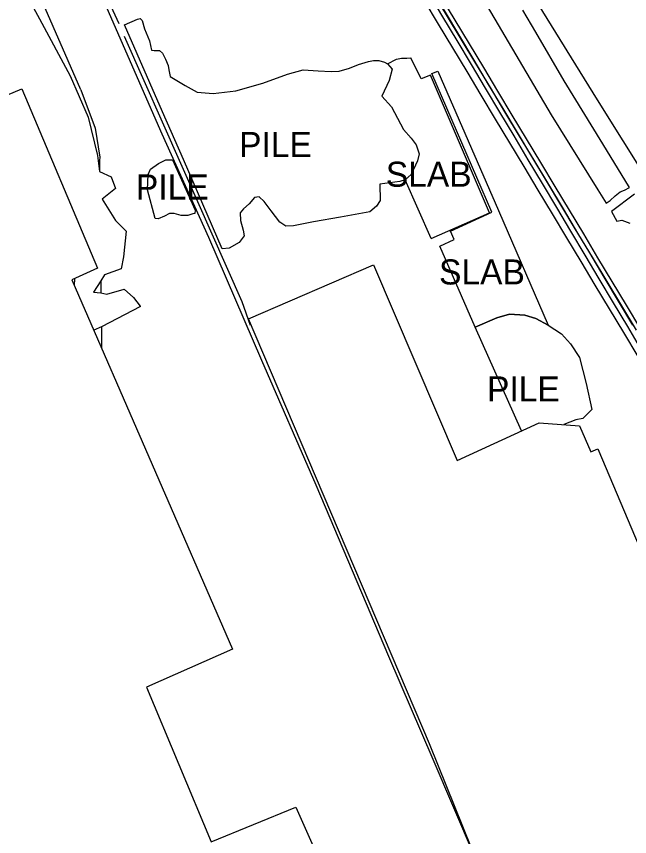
# Model space of a CAD drawing. Extents: x 368532 to 392481, y 10654822 to 10676899.
# Drawn here: x 378537.6 to 378659.8, y 10661264.3 to 10661427.9 of the extents above; entities that cross this region are included whole.
import ezdxf

# ---------------------------------------------------------------- set-up
doc = ezdxf.new("R2010")
doc.units = 0
for name, color, linetype in [('p_Catenary', 7, 'Continuous'), ('p_dtm retaining wall', 7, 'Continuous'), ('p_dtm sidewalk', 7, 'Continuous'), ('p_dtm slab', 7, 'Continuous'), ('p_dtm stock pile', 7, 'Continuous'), ('p_road - paved curb', 7, 'Continuous'), ('p_road general road feature', 7, 'Continuous'), ('p_structure building', 7, 'Continuous')]:
    doc.layers.add(name, color=color, linetype=linetype)

msp = doc.modelspace()

# ---------------------------------------------------------------- linework, layer by layer
at = {"layer": 'p_Catenary'}
for points in [[(378611.47, 10661447.94), (378614.35, 10661443.13), (378617.23, 10661438.33), (378620.1, 10661433.53), (378622.98, 10661428.73), (378625.86, 10661423.93), (378628.74, 10661419.12), (378631.61, 10661414.32), (378634.49, 10661409.52), (378637.37, 10661404.72), (378640.24, 10661399.92), (378643.12, 10661395.11), (378646, 10661390.31), (378648.88, 10661385.51), (378651.75, 10661380.71), (378654.63, 10661375.91), (378657.51, 10661371.11), (378660.38, 10661366.3)], [(378611.59, 10661447.53), (378614.5, 10661442.7), (378617.41, 10661437.86), (378620.32, 10661433.03), (378623.23, 10661428.19), (378626.13, 10661423.36), (378629.04, 10661418.52), (378631.95, 10661413.69), (378634.86, 10661408.85), (378637.77, 10661404.02), (378640.68, 10661399.18), (378643.59, 10661394.35), (378646.5, 10661389.51), (378649.41, 10661384.68), (378652.32, 10661379.84), (378655.23, 10661375.01), (378658.14, 10661370.17), (378661.05, 10661365.34)], [(378611.17, 10661446.81), (378614.01, 10661442.06), (378616.84, 10661437.31), (378619.67, 10661432.56), (378622.51, 10661427.81), (378625.34, 10661423.06), (378628.17, 10661418.31), (378631.01, 10661413.55), (378633.84, 10661408.8), (378636.67, 10661404.05), (378639.51, 10661399.3), (378642.34, 10661394.55), (378645.17, 10661389.8), (378648.01, 10661385.05), (378650.84, 10661380.29), (378653.67, 10661375.54), (378656.51, 10661370.79), (378659.34, 10661366.04), (378662.17, 10661361.29)], [(378613.55, 10661446.12), (378616.39, 10661441.38), (378619.24, 10661436.64), (378622.09, 10661431.9), (378624.93, 10661427.16), (378627.78, 10661422.42), (378630.63, 10661417.68), (378633.47, 10661412.94), (378636.32, 10661408.2), (378639.16, 10661403.46), (378642.01, 10661398.72), (378644.86, 10661393.98), (378647.7, 10661389.24), (378650.55, 10661384.5), (378653.4, 10661379.76), (378656.24, 10661375.02), (378659.09, 10661370.28), (378661.94, 10661365.54)], [(378610.27, 10661445.29), (378613.11, 10661440.56), (378615.95, 10661435.83), (378618.79, 10661431.09), (378621.63, 10661426.36), (378624.47, 10661421.62), (378627.31, 10661416.89), (378630.15, 10661412.16), (378632.99, 10661407.42), (378635.83, 10661402.69), (378638.67, 10661397.95), (378641.51, 10661393.22), (378644.35, 10661388.49), (378647.19, 10661383.75), (378650.03, 10661379.02), (378652.87, 10661374.28), (378655.71, 10661369.55), (378658.55, 10661364.82), (378661.39, 10661360.08)]]:
    msp.add_lwpolyline(points, dxfattribs=at)
at = {"layer": 'p_dtm retaining wall'}
for p, q in [((378540.16, 10661466.05), (378557.94, 10661426.45)), ((378559.05, 10661423.95), (378570.53, 10661398.01)), ((378570.53, 10661398.01), (378582.46, 10661371.06)), ((378582.46, 10661371.06), (378584.15, 10661366.3))]:
    msp.add_line(p, q, dxfattribs=at)
at = {"layer": 'p_dtm sidewalk'}
for p, q in [((378631.35, 10661429.9), (378644.17, 10661408.24)), ((378641.06, 10661424.73), (378638.51, 10661429.1)), ((378646.75, 10661415.06), (378641.06, 10661424.73)), ((378654.46, 10661402.48), (378646.75, 10661415.06)), ((378644.17, 10661408.24), (378653.41, 10661393.29)), ((378659.73, 10661393.79), (378654.46, 10661402.48)), ((378653.41, 10661393.29), (378655.07, 10661390.65)), ((378657.91, 10661392.87), (378658.77, 10661393.25)), ((378658.77, 10661393.25), (378659.73, 10661393.79)), ((378655.88, 10661391.19), (378656.88, 10661392.1)), ((378660.73, 10661392.41), (378656.17, 10661388.96)), ((378656.88, 10661392.1), (378657.91, 10661392.87)), ((378655.07, 10661390.65), (378655.88, 10661391.19)), ((378656.17, 10661388.96), (378657.2, 10661387.07)), ((378657.2, 10661387.07), (378658.25, 10661387.28)), ((378658.25, 10661387.28), (378659.81, 10661386.62))]:
    msp.add_line(p, q, dxfattribs=at)
at = {"layer": 'p_dtm slab'}
for p, q in [((378611.5, 10661418.45), (378613.29, 10661419.37)), ((378613.29, 10661419.37), (378614.33, 10661419.54)), ((378614.33, 10661419.54), (378615.4, 10661419.56)), ((378615.4, 10661419.56), (378616.2, 10661419.65)), ((378618.22, 10661415.4), (378616.2, 10661419.65)), ((378620.11, 10661416.15), (378618.22, 10661415.4)), ((378631.88, 10661388.69), (378620.11, 10661416.15)), ((378620.33, 10661416.47), (378621.52, 10661416.99)), ((378632.28, 10661388.82), (378620.33, 10661416.47)), ((378621.52, 10661416.99), (378633.62, 10661389.18)), ((378620.23, 10661383.6), (378615.04, 10661395.29)), ((378620.23, 10661383.6), (378631.88, 10661388.69)), ((378624.06, 10661385.05), (378632.28, 10661388.82)), ((378633.62, 10661389.18), (378643.52, 10661366.34)), ((378624.82, 10661383.42), (378624.06, 10661385.05)), ((378621.98, 10661382.03), (378624.82, 10661383.42)), ((378629.02, 10661365.93), (378621.98, 10661382.03)), ((378635.84, 10661368.5), (378633.3, 10661367.74)), ((378638.89, 10661368.31), (378635.84, 10661368.5)), ((378633.3, 10661367.74), (378629.02, 10661365.93)), ((378641.08, 10661367.67), (378638.89, 10661368.31)), ((378643.52, 10661366.34), (378641.08, 10661367.67))]:
    msp.add_line(p, q, dxfattribs=at)
at = {"layer": 'p_dtm stock pile'}
for p, q in [((378537.92, 10661435.15), (378542.16, 10661427.37)), ((378542.16, 10661427.37), (378548.27, 10661416.05)), ((378561.68, 10661427.34), (378562.25, 10661427.46)), ((378562.25, 10661427.46), (378562.61, 10661427.04)), ((378559.12, 10661426.23), (378561.68, 10661427.34)), ((378566.68, 10661408.82), (378559.12, 10661426.23)), ((378562.61, 10661427.04), (378563.07, 10661425.39)), ((378563.07, 10661425.39), (378564.06, 10661423.04)), ((378564.06, 10661423.04), (378564.5, 10661421.12)), ((378564.5, 10661421.12), (378564.98, 10661421.07)), ((378564.98, 10661421.07), (378566.09, 10661421.11)), ((378566.09, 10661421.11), (378566.68, 10661420.55)), ((378566.68, 10661420.55), (378567.3, 10661419.35)), ((378567.3, 10661419.35), (378567.77, 10661418.09)), ((378567.77, 10661418.09), (378567.95, 10661417.25)), ((378603.96, 10661417.54), (378605.76, 10661418.26)), ((378605.76, 10661418.26), (378607.73, 10661418.92)), ((378607.73, 10661418.92), (378608.72, 10661419.1)), ((378608.72, 10661419.1), (378609.8, 10661419.09)), ((378609.8, 10661419.09), (378610.93, 10661418.76)), ((378610.93, 10661418.76), (378611.5, 10661418.45)), ((378611.5, 10661418.45), (378612.48, 10661417.39)), ((378548.27, 10661416.05), (378551.88, 10661407.78)), ((378567.95, 10661417.25), (378568.22, 10661415.9)), ((378586.67, 10661414.58), (378591.57, 10661416.35)), ((378591.57, 10661416.35), (378594.72, 10661417.22)), ((378594.72, 10661417.22), (378597.67, 10661417)), ((378597.67, 10661417), (378600.28, 10661416.87)), ((378600.28, 10661416.87), (378601.87, 10661416.94)), ((378601.87, 10661416.94), (378603.96, 10661417.54)), ((378612.48, 10661417.39), (378611.86, 10661415.09)), ((378568.22, 10661415.9), (378571.2, 10661414.1)), ((378581.27, 10661413.02), (378586.67, 10661414.58)), ((378611.86, 10661415.09), (378610.38, 10661411.97)), ((378571.2, 10661414.1), (378573.57, 10661412.8)), ((378573.57, 10661412.8), (378576.74, 10661412.53)), ((378576.74, 10661412.53), (378581.27, 10661413.02)), ((378610.38, 10661411.97), (378612.3, 10661409.85)), ((378612.3, 10661409.85), (378614.7, 10661405.3)), ((378551.88, 10661407.78), (378553.69, 10661400.11)), ((378570.84, 10661399.37), (378566.68, 10661408.82)), ((378614.7, 10661405.3), (378616.25, 10661403.57)), ((378616.25, 10661403.57), (378617.24, 10661402.27)), ((378617.24, 10661402.27), (378617.8, 10661400.5)), ((378553.69, 10661400.11), (378554.11, 10661396.98)), ((378617.8, 10661400.5), (378617.52, 10661399.1)), ((378564.28, 10661397.45), (378565.85, 10661398.57)), ((378565.85, 10661398.57), (378567.34, 10661399.26)), ((378567.34, 10661399.26), (378568.66, 10661399.3)), ((378568.66, 10661399.3), (378573.17, 10661389.21)), ((378578.54, 10661381.51), (378570.84, 10661399.37)), ((378617.52, 10661399.1), (378616.24, 10661396.35)), ((378554.11, 10661396.98), (378556.43, 10661395.88)), ((378563.68, 10661393.3), (378563.79, 10661396.33)), ((378563.79, 10661396.33), (378564.28, 10661397.45)), ((378616.24, 10661396.35), (378615.04, 10661395.29)), ((378556.43, 10661395.88), (378557.32, 10661393.55)), ((378614, 10661394.99), (378609.97, 10661394.44)), ((378615.04, 10661395.29), (378614, 10661394.99)), ((378557.32, 10661393.55), (378554.63, 10661391.43)), ((378565.18, 10661387.6), (378563.68, 10661393.3)), ((378609.97, 10661394.44), (378610.05, 10661391.2)), ((378554.63, 10661391.43), (378557.33, 10661387.21)), ((378585.01, 10661391.75), (378583.94, 10661390.53)), ((378585.93, 10661391.88), (378585.01, 10661391.75)), ((378586.91, 10661390.98), (378585.93, 10661391.88)), ((378583.94, 10661390.53), (378582.84, 10661389.51)), ((378588.32, 10661389.12), (378586.91, 10661390.98)), ((378609.32, 10661390.06), (378608.01, 10661388.92)), ((378610.05, 10661391.2), (378609.32, 10661390.06)), ((378568.04, 10661388.59), (378567.09, 10661388.07)), ((378569.03, 10661388.56), (378568.04, 10661388.59)), ((378570.4, 10661388.16), (378569.03, 10661388.56)), ((378571.71, 10661388.19), (378570.4, 10661388.16)), ((378572.75, 10661388.48), (378571.71, 10661388.19)), ((378573.1, 10661388.59), (378572.75, 10661388.48)), ((378573.17, 10661389.21), (378573.1, 10661388.59)), ((378582.84, 10661389.51), (378582.14, 10661388.71)), ((378582.14, 10661388.71), (378582.24, 10661387.19)), ((378590.07, 10661386.86), (378588.32, 10661389.12)), ((378608.01, 10661388.92), (378602.18, 10661387.84)), ((378557.33, 10661387.21), (378559.44, 10661385.07)), ((378565.79, 10661387.53), (378565.18, 10661387.6)), ((378567.09, 10661388.07), (378565.79, 10661387.53)), ((378582.24, 10661387.19), (378582.74, 10661385.25)), ((378591.24, 10661386.04), (378590.07, 10661386.86)), ((378596.8, 10661386.94), (378592.81, 10661386.13)), ((378602.18, 10661387.84), (378596.8, 10661386.94)), ((378559.44, 10661385.07), (378558.89, 10661379.91)), ((378582.74, 10661385.25), (378582.96, 10661384.09)), ((378592.81, 10661386.13), (378591.24, 10661386.04)), ((378582.96, 10661384.09), (378581.95, 10661382.77)), ((378579.93, 10661381.68), (378578.54, 10661381.51)), ((378581.95, 10661382.77), (378579.93, 10661381.68)), ((378558.89, 10661379.91), (378558.43, 10661377.53)), ((378558.43, 10661377.53), (378555.12, 10661376.37)), ((378549.13, 10661374.18), (378549.2, 10661375.62)), ((378554.38, 10661375.16), (378552.89, 10661372.91)), ((378555.12, 10661376.37), (378554.38, 10661375.16)), ((378555.61, 10661372.52), (378559.02, 10661373.49)), ((378559.02, 10661373.49), (378560.86, 10661371.85)), ((378552.89, 10661372.91), (378554.4, 10661372.78)), ((378554.4, 10661372.78), (378555.61, 10661372.52)), ((378560.86, 10661371.85), (378562.25, 10661370.1)), ((378562.28, 10661370.02), (378554.49, 10661365.97)), ((378562.25, 10661370.1), (378562.28, 10661370.02)), ((378633.3, 10661367.74), (378635.84, 10661368.5)), ((378635.84, 10661368.5), (378638.89, 10661368.31)), ((378629.02, 10661365.93), (378633.3, 10661367.74)), ((378638.89, 10661368.31), (378641.08, 10661367.67)), ((378641.08, 10661367.67), (378643.52, 10661366.34)), ((378554.49, 10661365.97), (378552.97, 10661365.34)), ((378638.22, 10661345.24), (378629.02, 10661365.93)), ((378643.52, 10661366.34), (378646.23, 10661364.61)), ((378646.23, 10661364.61), (378648, 10661362.6)), ((378648, 10661362.6), (378649.77, 10661359.86)), ((378649.77, 10661359.86), (378651.14, 10661354.69)), ((378651.14, 10661354.69), (378652.22, 10661349.48)), ((378652.22, 10661349.48), (378650.44, 10661347.73)), ((378649.05, 10661347.43), (378646.63, 10661346.47)), ((378650.44, 10661347.73), (378649.05, 10661347.43))]:
    msp.add_line(p, q, dxfattribs=at)
at = {"layer": 'p_road - paved curb'}
for p, q in [((378653.4, 10661411.22), (378639.64, 10661433.52)), ((378671.52, 10661382.17), (378653.4, 10661411.22))]:
    msp.add_line(p, q, dxfattribs=at)
at = {"layer": 'p_road general road feature'}
for p, q in [((378550.42, 10661413.24), (378537.82, 10661441.96)), ((378554.07, 10661433.07), (378566.57, 10661404.49)), ((378550.42, 10661413.24), (378553.23, 10661405.58)), ((378553.23, 10661405.58), (378554.18, 10661399.82)), ((378566.57, 10661404.49), (378575.83, 10661383.89)), ((378554.18, 10661399.82), (378554.09, 10661399.13)), ((378554.09, 10661399.13), (378554.11, 10661396.98)), ((378575.83, 10661383.89), (378586.38, 10661359.33)), ((378554.38, 10661375.16), (378554.4, 10661372.78)), ((378554.49, 10661365.97), (378554.54, 10661361.74)), ((378586.38, 10661359.33), (378597.22, 10661334.48)), ((378597.22, 10661334.48), (378611.7, 10661300.29)), ((378611.7, 10661300.29), (378620.58, 10661279.79)), ((378620.58, 10661279.79), (378629.9, 10661257.83))]:
    msp.add_line(p, q, dxfattribs=at)
at = {"layer": 'p_structure building'}
for points in [[(378506.18, 10661459.09), (378527.57, 10661408.8), (378538.63, 10661413.42), (378553.69, 10661377.67), (378548.62, 10661375.35), (378580.63, 10661301.69), (378563.47, 10661294.09), (378576.35, 10661263.29), (378593.24, 10661270.21), (378607.72, 10661237.58)], [(378630.01, 10661257.76), (378619.88, 10661282.83), (378583.81, 10661367.58), (378608.72, 10661378.31), (378625.39, 10661339.34), (378641.75, 10661346.86), (378649.79, 10661346.21), (378652.06, 10661341.02), (378653.42, 10661341.67), (378669.19, 10661304.42), (378686.72, 10661312.06), (378697.59, 10661288.04), (378699.33, 10661288.82), (378720.56, 10661239.23)]]:
    msp.add_lwpolyline(points, dxfattribs=at)

# ---------------------------------------------------------------- texts
at = {"layer": 'p_dtm slab'}
for p in [(378609.33, 10661393.91), (378619.94, 10661374.42)]:
    msp.add_text(' SLAB', height=5, dxfattribs=at).set_placement(p)
at = {"layer": 'p_dtm stock pile'}
for p in [(378580.08, 10661399.84), (378559.52, 10661391.36), (378629.5, 10661351.09)]:
    msp.add_text(' PILE', height=5, dxfattribs=at).set_placement(p)

doc.saveas('drawing.dxf')
